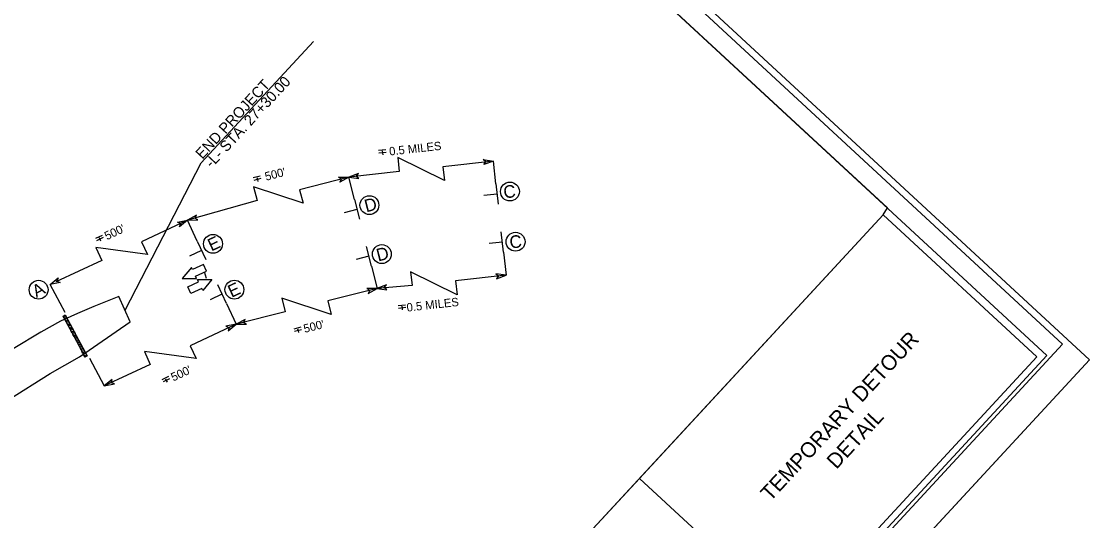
# Model space of a CAD drawing. Extents: x 1767460 to 1770129, y 996106 to 1001438.
# Drawn here: x 1769280 to 1770129, y 1000408 to 1000805 of the extents above; entities that cross this region are included whole.
import ezdxf

# ---------------------------------------------------------------- set-up
doc = ezdxf.new("R2010")
doc.units = 0
for name, color, linetype in [('_CIVIL_CONSTRUCTION', 7, 'Continuous'), ('E_NCDOT_Terrain_Model_Contour_Major', 7, 'Continuous'), ('E_NCDOT_Terrain_Model_Contour_Minor', 7, 'Continuous'), ('E_NCDOT_Terrain_Model_Points_Low', 7, 'Continuous'), ('E_NCDOT_Terrain_Model_Spot_Elevation', 7, 'Continuous'), ('E_NCDOT_Terrain_Model_Triangle_Vertices', 7, 'Continuous'), ('E_NCDOT_Terrain_Model_Triangles', 7, 'Continuous'), ('P_NCDOT_Terrain_Island', 7, 'Continuous'), ('P_NCDOT_Terrain_Points_High', 7, 'Continuous'), ('P_RDY_TL_Edge_of_Travel_Sub', 7, 'Continuous'), ('P_RDY_TL_Grass_Shoulder_Normal', 7, 'Continuous')]:
    doc.layers.add(name, color=color, linetype=linetype)

msp = doc.modelspace()

# ---------------------------------------------------------------- linework, layer by layer
at = {"layer": '_CIVIL_CONSTRUCTION'}
for centre in [(1769668.44, 1000669.69), (1769556.84, 1000658.88), (1769672.9, 1000629.82), (1769432.63, 1000628.12), (1769566.72, 1000620), (1769294.16, 1000591.7), (1769449.61, 1000591.77)]:
    msp.add_circle(centre, 7.5, dxfattribs=at)
at = {"layer": 'E_NCDOT_Terrain_Model_Contour_Major'}
for points in [[(1769357.91, 1000586.38), (1769338.11, 1000578.35), (1769325, 1000572.73), (1769311.52, 1000566.7), (1769296.01, 1000557.91), (1769273.97, 1000544.69)], [(1769326.61, 1000538.51), (1769366.87, 1000566.15), (1769357.91, 1000586.38)], [(1769269.74, 1000504.03), (1769303.4, 1000525.13), (1769326.61, 1000538.51)]]:
    msp.add_lwpolyline(points, dxfattribs=at)
at = {"layer": 'E_NCDOT_Terrain_Model_Contour_Minor'}
msp.add_lwpolyline([(1768744.05, 999038.07), (1770128.77, 1000536.12), (1769152.55, 1001438.49), (1767767.83, 999940.44)], close=True, dxfattribs=at)
at = {"layer": 'E_NCDOT_Terrain_Model_Points_Low'}
msp.add_lwpolyline([(1767804.38, 999935.46), (1769171.05, 1001413.98), (1770107.33, 1000548.53), (1768740.66, 999070.01)], close=True, dxfattribs=at)
at = {"layer": 'E_NCDOT_Terrain_Model_Spot_Elevation'}
for p, q in [((1769313.58, 1000570.82), (1769315.19, 1000571.68)), ((1769314.37, 1000569.36), (1769313.58, 1000570.82)), ((1769313.58, 1000570.82), (1769316.09, 1000570.06)), ((1769322.3, 1000554.52), (1769313.58, 1000570.82)), ((1769316.87, 1000568.6), (1769314.37, 1000569.36)), ((1769315.19, 1000571.68), (1769323.9, 1000555.38)), ((1769316.09, 1000570.06), (1769316.87, 1000568.6)), ((1769315.94, 1000566.42), (1769315.15, 1000567.89)), ((1769315.15, 1000567.89), (1769317.66, 1000567.13)), ((1769318.44, 1000565.66), (1769315.94, 1000566.42)), ((1769317.52, 1000563.46), (1769316.74, 1000564.93)), ((1769316.74, 1000564.93), (1769319.23, 1000564.19)), ((1769320.01, 1000562.73), (1769317.52, 1000563.46)), ((1769317.66, 1000567.13), (1769318.44, 1000565.66)), ((1769319.09, 1000560.53), (1769318.3, 1000561.99)), ((1769318.3, 1000561.99), (1769320.8, 1000561.26)), ((1769321.58, 1000559.79), (1769319.09, 1000560.53)), ((1769319.23, 1000564.19), (1769320.01, 1000562.73)), ((1769320.8, 1000561.26), (1769321.58, 1000559.79)), ((1769320.66, 1000557.59), (1769319.87, 1000559.06)), ((1769319.87, 1000559.06), (1769322.36, 1000558.33)), ((1769323.15, 1000556.86), (1769320.66, 1000557.59)), ((1769322.3, 1000554.52), (1769321.44, 1000556.13)), ((1769321.44, 1000556.13), (1769323.93, 1000555.39)), ((1769323.93, 1000555.39), (1769322.3, 1000554.52)), ((1769322.3, 1000554.52), (1769323.9, 1000555.38)), ((1769323.9, 1000555.38), (1769322.3, 1000554.52)), ((1769323.08, 1000553.05), (1769322.3, 1000554.52)), ((1769322.3, 1000554.52), (1769324.81, 1000553.76)), ((1769331.02, 1000538.22), (1769322.3, 1000554.52)), ((1769322.36, 1000558.33), (1769323.15, 1000556.86)), ((1769325.59, 1000552.29), (1769323.08, 1000553.05)), ((1769323.9, 1000555.38), (1769332.62, 1000539.08)), ((1769324.81, 1000553.76), (1769325.59, 1000552.29)), ((1769324.65, 1000550.12), (1769323.87, 1000551.59)), ((1769323.87, 1000551.59), (1769326.37, 1000550.83)), ((1769327.16, 1000549.36), (1769324.65, 1000550.12)), ((1769326.24, 1000547.16), (1769325.45, 1000548.63)), ((1769325.45, 1000548.63), (1769327.94, 1000547.89)), ((1769328.73, 1000546.43), (1769326.24, 1000547.16)), ((1769326.37, 1000550.83), (1769327.16, 1000549.36)), ((1769327.8, 1000544.22), (1769327.02, 1000545.69)), ((1769327.02, 1000545.69), (1769329.51, 1000544.96)), ((1769330.3, 1000543.49), (1769327.8, 1000544.22)), ((1769327.94, 1000547.89), (1769328.73, 1000546.43)), ((1769329.51, 1000544.96), (1769330.3, 1000543.49)), ((1769329.37, 1000541.29), (1769328.59, 1000542.76)), ((1769328.59, 1000542.76), (1769331.08, 1000542.03)), ((1769331.86, 1000540.56), (1769329.37, 1000541.29)), ((1769331.02, 1000538.22), (1769330.16, 1000539.82)), ((1769330.16, 1000539.82), (1769332.65, 1000539.09)), ((1769332.65, 1000539.09), (1769331.02, 1000538.22)), ((1769332.62, 1000539.08), (1769331.02, 1000538.22)), ((1769331.08, 1000542.03), (1769331.86, 1000540.56))]:
    msp.add_line(p, q, dxfattribs=at)
at = {"layer": 'E_NCDOT_Terrain_Model_Triangle_Vertices'}
for p, q in [((1769657.29, 1000675.73), (1769659.09, 1000659.63)), ((1769544.96, 1000663.34), (1769548.95, 1000647.64)), ((1769658.19, 1000667.62), (1769647.76, 1000666.45)), ((1769546.97, 1000655.42), (1769536.8, 1000652.84)), ((1769663.36, 1000621.46), (1769661.56, 1000637.56)), ((1769420.13, 1000630.28), (1769426.99, 1000615.6)), ((1769662.45, 1000629.58), (1769652.02, 1000628.41)), ((1769423.59, 1000622.88), (1769414.08, 1000618.44)), ((1769558.42, 1000610.41), (1769554.43, 1000626.11)), ((1769556.41, 1000618.33), (1769546.23, 1000615.74)), ((1769443.24, 1000580.8), (1769436.38, 1000595.48)), ((1769439.78, 1000588.2), (1769430.27, 1000583.75))]:
    msp.add_line(p, q, dxfattribs=at)
for points in [[(1769163.02, 1001400.87), (1767932.52, 1000069.67), (1768864.37, 999208.32), (1770094.87, 1000539.52)], [(1769964.83, 1000651.25), (1769771.23, 1000441.81), (1769893.26, 1000329.01), (1770086.86, 1000538.45)], [(1769677.71, 1000340.64), (1769771.23, 1000441.81), (1769893.26, 1000329.01), (1769799.74, 1000227.84)]]:
    msp.add_lwpolyline(points, close=True, dxfattribs=at)
at = {"layer": 'E_NCDOT_Terrain_Model_Triangles'}
for p, q in [((1769423.2, 1000692.53), (1769512.31, 1000788.94)), ((1769569.91, 1000702.79), (1769564.19, 1000702.15)), ((1769570.14, 1000700.79), (1769564.41, 1000700.15)), ((1769567.1, 1000701.99), (1769567.27, 1000700.47)), ((1769567.27, 1000700.47), (1769567.44, 1000698.95)), ((1769362.77, 1000575.42), (1769423.2, 1000692.53)), ((1769655.25, 1000693.9), (1769615.16, 1000689.41)), ((1769647.14, 1000694.99), (1769655.25, 1000693.9)), ((1769649.34, 1000693.23), (1769647.14, 1000694.99)), ((1769655.25, 1000693.9), (1769647.59, 1000691.04)), ((1769647.59, 1000691.04), (1769649.34, 1000693.23)), ((1769657.29, 1000675.73), (1769655.25, 1000693.9)), ((1769470.19, 1000681.91), (1769464.6, 1000680.49)), ((1769470.68, 1000679.96), (1769465.1, 1000678.54)), ((1769467.52, 1000680.74), (1769467.89, 1000679.25)), ((1769467.89, 1000679.25), (1769468.27, 1000677.77)), ((1769540.46, 1000681.05), (1769501.36, 1000671.11)), ((1769532.28, 1000681.02), (1769540.46, 1000681.05)), ((1769534.69, 1000679.58), (1769532.28, 1000681.02)), ((1769540.46, 1000681.05), (1769533.26, 1000677.17)), ((1769533.26, 1000677.17), (1769534.69, 1000679.58)), ((1769580.55, 1000685.54), (1769540.46, 1000681.05)), ((1769548.13, 1000683.9), (1769540.46, 1000681.05)), ((1769544.96, 1000663.34), (1769540.46, 1000681.05)), ((1769540.46, 1000681.05), (1769548.57, 1000679.96)), ((1769546.38, 1000681.71), (1769548.13, 1000683.9)), ((1769548.57, 1000679.96), (1769546.38, 1000681.71)), ((1769467.61, 1000662.53), (1769412.4, 1000646.84)), ((1769412.4, 1000646.84), (1769375.85, 1000629.77)), ((1769404.37, 1000645.28), (1769412.4, 1000646.84)), ((1769407.01, 1000644.32), (1769404.37, 1000645.28)), ((1769412.4, 1000646.84), (1769406.05, 1000641.68)), ((1769419.49, 1000650.92), (1769412.4, 1000646.84)), ((1769412.4, 1000646.84), (1769420.58, 1000647.1)), ((1769420.13, 1000630.28), (1769412.4, 1000646.84)), ((1769418.13, 1000648.46), (1769419.49, 1000650.92)), ((1769420.58, 1000647.1), (1769418.13, 1000648.46)), ((1769406.05, 1000641.68), (1769407.01, 1000644.32)), ((1769344.54, 1000634.87), (1769339.32, 1000632.43)), ((1769345.39, 1000633.05), (1769340.17, 1000630.61)), ((1769342.13, 1000633.22), (1769342.78, 1000631.83)), ((1769342.78, 1000631.83), (1769343.43, 1000630.44)), ((1769663.36, 1000621.46), (1769665.39, 1000603.3)), ((1769344.29, 1000615.03), (1769307.74, 1000597.96)), ((1769558.42, 1000610.41), (1769562.92, 1000592.7)), ((1769665.39, 1000603.3), (1769625.3, 1000598.81)), ((1769665.39, 1000603.3), (1769657.28, 1000604.39)), ((1769657.28, 1000604.39), (1769659.48, 1000602.64)), ((1769657.72, 1000600.45), (1769665.39, 1000603.3)), ((1769659.48, 1000602.64), (1769657.72, 1000600.45)), ((1769303.27, 1000595.87), (1769309.62, 1000601.03)), ((1769311.3, 1000597.43), (1769303.27, 1000595.87)), ((1769315.12, 1000573.71), (1769303.27, 1000595.87)), ((1769309.62, 1000601.03), (1769308.66, 1000598.39)), ((1769308.66, 1000598.39), (1769311.3, 1000597.43)), ((1769570.31, 1000595.59), (1769562.64, 1000592.74)), ((1769590.69, 1000594.94), (1769562.92, 1000592.7)), ((1769568.56, 1000593.4), (1769570.31, 1000595.59)), ((1769562.92, 1000592.7), (1769523.82, 1000582.76)), ((1769562.92, 1000592.7), (1769554.74, 1000592.67)), ((1769554.74, 1000592.67), (1769557.15, 1000591.23)), ((1769555.72, 1000588.82), (1769562.92, 1000592.7)), ((1769557.15, 1000591.23), (1769555.72, 1000588.82)), ((1769562.64, 1000592.74), (1769570.75, 1000591.65)), ((1769570.75, 1000591.65), (1769568.56, 1000593.4)), ((1769443.24, 1000580.8), (1769450.97, 1000564.24)), ((1769585.43, 1000579.51), (1769579.7, 1000578.86)), ((1769585.65, 1000577.51), (1769579.93, 1000576.87)), ((1769582.62, 1000578.71), (1769582.79, 1000577.19)), ((1769582.79, 1000577.19), (1769582.96, 1000575.67)), ((1769490.07, 1000574.18), (1769450.97, 1000564.24)), ((1769450.97, 1000564.24), (1769414.42, 1000547.17)), ((1769450.97, 1000564.24), (1769442.94, 1000562.68)), ((1769442.94, 1000562.68), (1769445.58, 1000561.72)), ((1769444.62, 1000559.08), (1769450.97, 1000564.24)), ((1769445.58, 1000561.72), (1769444.62, 1000559.08)), ((1769458.18, 1000568.12), (1769450.97, 1000564.24)), ((1769450.97, 1000564.24), (1769459.15, 1000564.27)), ((1769456.74, 1000565.71), (1769458.18, 1000568.12)), ((1769459.15, 1000564.27), (1769456.74, 1000565.71)), ((1769502.46, 1000561.91), (1769496.88, 1000560.49)), ((1769499.79, 1000560.74), (1769500.16, 1000559.26)), ((1769502.96, 1000559.97), (1769497.37, 1000558.55)), ((1769500.16, 1000559.26), (1769500.54, 1000557.77)), ((1769334.52, 1000537.41), (1769346.31, 1000515.36)), ((1769382.86, 1000532.43), (1769346.31, 1000515.36)), ((1769352.66, 1000520.52), (1769346.31, 1000515.36)), ((1769351.7, 1000517.88), (1769352.66, 1000520.52)), ((1769354.34, 1000516.92), (1769351.7, 1000517.88)), ((1769397.33, 1000522.7), (1769392.11, 1000520.26)), ((1769398.18, 1000520.88), (1769392.96, 1000518.44)), ((1769394.92, 1000521.05), (1769395.57, 1000519.66)), ((1769395.57, 1000519.66), (1769396.22, 1000518.27)), ((1769346.31, 1000515.36), (1769354.34, 1000516.92))]:
    msp.add_line(p, q, dxfattribs=at)
for points in [[(1769615.16, 1000689.41), (1769616.4, 1000678.33), (1769579.31, 1000696.61), (1769580.55, 1000685.54)], [(1769501.36, 1000671.11), (1769504.11, 1000660.31), (1769464.86, 1000673.33), (1769467.61, 1000662.53)], [(1769375.85, 1000629.77), (1769380.56, 1000619.67), (1769339.58, 1000625.13), (1769344.29, 1000615.03)], [(1769625.3, 1000598.81), (1769626.54, 1000587.74), (1769589.45, 1000606.02), (1769590.69, 1000594.94)], [(1769523.82, 1000582.76), (1769526.57, 1000571.96), (1769487.32, 1000584.98), (1769490.07, 1000574.18)], [(1769414.42, 1000547.17), (1769419.14, 1000537.07), (1769378.15, 1000542.53), (1769382.86, 1000532.43)]]:
    msp.add_lwpolyline(points, dxfattribs=at)
at = {"layer": 'P_NCDOT_Terrain_Island'}
msp.add_line((1769427.55, 1000600.57), (1769425.91, 1000605.84), dxfattribs=at)
at = {"layer": 'P_NCDOT_Terrain_Points_High'}
msp.add_line((1768744.05, 999038.07), (1770128.77, 1000536.12), dxfattribs=at)
msp.add_lwpolyline([(1769163.02, 1001400.87), (1767932.52, 1000069.67), (1768864.37, 999208.32), (1769639.43, 1000046.81), (1769513.61, 1000163.11), (1769964.83, 1000651.25), (1769968.19, 1000656.62)], close=True, dxfattribs=at)
at = {"layer": 'P_RDY_TL_Grass_Shoulder_Normal'}
for p, q in [((1769425.08, 1000611.73), (1769416.38, 1000607.67)), ((1769427.53, 1000606.48), (1769425.08, 1000611.73)), ((1769415.54, 1000609.46), (1769408.24, 1000600.67)), ((1769416.38, 1000607.67), (1769415.54, 1000609.46)), ((1769418.83, 1000602.42), (1769427.53, 1000606.48)), ((1769408.24, 1000600.67), (1769419.66, 1000600.63)), ((1769412.54, 1000593.97), (1769421.24, 1000598.03)), ((1769419.66, 1000600.63), (1769418.83, 1000602.42)), ((1769421.24, 1000598.03), (1769420.41, 1000599.81)), ((1769420.41, 1000599.81), (1769431.83, 1000599.78)), ((1769431.83, 1000599.78), (1769424.53, 1000590.99)), ((1769414.99, 1000588.72), (1769412.54, 1000593.97)), ((1769423.69, 1000592.78), (1769414.99, 1000588.72)), ((1769424.53, 1000590.99), (1769423.69, 1000592.78))]:
    msp.add_line(p, q, dxfattribs=at)

# ---------------------------------------------------------------- texts
at = {"layer": '_CIVIL_CONSTRUCTION'}
for s, rotation, p in [('C', 6.38519, (1769663.83, 1000664.21)), ('D', 14.26418, (1769554.31, 1000653.14)), ('E', 25.03161, (1769431.37, 1000621.99)), ('C', 6.38519, (1769668.66, 1000624.39)), ('D', 14.26418, (1769563.79, 1000614.09)), ('A', 28.1326, (1769292.41, 1000585.09)), ('E', 25.03161, (1769447.34, 1000585.19))]:
    msp.add_text(s, height=10, rotation=rotation, dxfattribs=at).set_placement(p)
at = {"layer": 'E_NCDOT_Terrain_Model_Triangles'}
for s, height, rotation, p in [('END PROJECT', 8.5, 47.25123, (1769424.16, 1000694.88)), ('-L- STA. 27+30.00', 8.5, 47.25123, (1769431.69, 1000687.92)), ('0.5 MILES', 6.667, 6.38519, (1769572.91, 1000698.23)), ("500'", 6.667, 14.26418, (1769474.76, 1000678.22)), ("500'", 6.667, 25.03161, (1769348.37, 1000630.95)), ('0.5 MILES', 6.667, 6.38519, (1769586.78, 1000574.24)), ("500'", 6.667, 14.26418, (1769505.49, 1000557.35)), ("500'", 6.667, 25.03161, (1769401.15, 1000518.78))]:
    msp.add_text(s, height=height, rotation=rotation, dxfattribs=at).set_placement(p)
at = {"layer": 'P_RDY_TL_Edge_of_Travel_Sub'}
for s, height, p in [('TEMPORARY DETOUR', 12.0853, (1769875.23, 1000423.01)), ('DETAIL', 12.085, (1769927.67, 1000448.58))]:
    msp.add_text(s, height=height, rotation=47.25123, dxfattribs=at).set_placement(p)

doc.saveas('drawing.dxf')
